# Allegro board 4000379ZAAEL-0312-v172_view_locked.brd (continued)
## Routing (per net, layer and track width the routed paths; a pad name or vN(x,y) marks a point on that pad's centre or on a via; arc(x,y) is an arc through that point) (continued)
DDR_A5: length 88
  TOP w0.102: U13.P2 96.57,25.59 96.96,25.99 v1(96.96,26.02) ; v1(103.76,36.75) 103.94,36.93 103.94,37.49 102.58,38.85 102.58,43.55 102.62,43.59 U1.B20 ; v1(117.34,26.02) 117.34,25.99 116.94,25.59 U12.P2
  BOTTOM w0.102: R110.2 121.34,27.64 121.31,27.64 121.16,27.49 119.39,27.49 118.45,26.55 117.43,26.55 117.34,26.46 v1(117.34,26.02) 117.17,26.02 116.73,25.58 116.4,25.58 116.11,25.86 116.11,26.26 115.84,26.53 115.3,26.53 114.32,27.52 112.45,27.52 111.27,28.7 109.2,28.7 108.29,27.79 103.91,27.79 103.84,27.71 103.84,27.28 103.76,27.2 103.5,27.2 103.43,27.28 103.43,27.71 103.35,27.79 102.54,27.79 102.46,27.71 102.46,27.43 102.54,27.36 102.95,27.36 103.02,27.28 103.02,26.97 102.95,26.9 102.11,26.9 101.3,26.09 97.06,26.09 97,26.02 v1(96.96,26.02) 96.95,26.01 96.84,26.01 96.38,25.56 96.02,25.56 95.73,25.84 95.73,26.21 95.52,26.43 94.83,26.43 93.76,27.51 91.97,27.51 91.57,27.91 91.57,28.05 90.53,29.09 90.53,31.57 90.6,31.65 93.65,31.65 93.73,31.72 93.73,33.93 93.8,34.01 99.14,34.01 99.21,34.09 99.21,35.23 99.29,35.31 101.57,35.31 101.65,35.38 101.65,35.89 101.73,35.97 104.39,35.97 104.47,36.04 104.47,36.45 104.55,36.53 109.55,36.53 109.63,36.6 109.63,37.85 109.7,37.92 109.86,37.92 109.93,38 109.93,38.25 109.86,38.33 109.7,38.33 109.63,38.4 109.63,38.66 109.7,38.73 109.86,38.73 109.93,38.81 109.93,39.07 109.86,39.14 109.3,39.14 109.22,39.07 109.22,36.98 109.14,36.91 108.89,36.91 108.81,36.98 108.81,37.74 108.74,37.82 108.48,37.82 108.41,37.74 108.41,36.98 108.33,36.91 103.91,36.91 v1(103.76,36.75)
DDR_A6: length 93
  TOP w0.102: U12.R8 112.14,26.39 112.5,26.75 112.5,28.35 v1(112.51,28.36) ; v1(103.1,34.85) 103.59,35.34 103.59,35.92 104.04,36.37 104.34,36.37 104.47,36.5 104.47,37.39 102.81,39.05 102.81,44.22 102.97,44.38 102.97,44.58 102.62,44.92 102.62,45.33 U1.D20 ; v1(92.18,28.24) 92.15,28.22 92.15,26.77 91.77,26.39 U13.R8
  BOTTOM w0.102: R111.2 121.36,28.53 118.78,28.53 118.7,28.45 118.7,27.54 118.18,27.02 115.39,27.02 114.49,27.93 113.12,27.93 112.69,28.36 v1(112.51,28.36) 112.22,28.36 111.47,29.11 109,29.11 108.14,28.24 101.22,28.24 101.14,28.17 101.14,27.71 101.04,27.61 100.61,27.61 100.48,27.74 98.52,27.74 97.66,26.89 94.95,26.89 93.92,27.91 92.75,27.91 92.68,27.98 92.57,27.98 92.51,27.91 92.37,27.91 92.18,28.11 v1(92.18,28.24) 91.97,28.24 91.14,29.08 91.14,30.96 91.21,31.04 94.26,31.04 94.34,31.11 94.34,33.32 94.41,33.4 99.75,33.4 99.82,33.48 99.82,34.62 99.9,34.7 102.41,34.7 102.49,34.77 102.49,35.28 102.57,35.36 103.63,35.36 103.71,35.28 103.71,35.15 103.78,35.08 104.78,35.08 104.85,35.15 104.85,36.22 104.93,36.3 110.16,36.3 110.24,36.37 110.24,37.39 110.31,37.47 110.57,37.47 110.64,37.39 110.64,36.37 110.72,36.3 110.97,36.3 111.05,36.37 111.05,37.39 111.12,37.47 111.38,37.47 111.46,37.39 111.46,35.97 111.38,35.89 105.31,35.89 105.23,35.81 105.23,34.77 105.16,34.7 103.25,34.7 v1(103.1,34.85)
DDR_A7: length 84.6
  TOP w0.102: v1(103.1,33.02) 103.4,33.32 103.4,34.4 103.87,34.87 103.87,35.84 104.1,36.06 104.62,36.06 104.78,36.22 104.78,37.52 103.05,39.24 103.05,43.78 U1.A19 ; v1(117.42,28.24) 117.42,28.24 117.4,28.24 117.32,28.17 117.32,26.77 116.94,26.39 U12.R2 ; U13.R2 96.57,26.39 96.96,26.78 96.96,28.15 97.04,28.23 v1(97.04,28.24)
  BOTTOM w0.102: v1(103.1,33.02) 103.53,33.02 104.25,32.26 111.63,32.26 111.71,32.18 111.71,31.93 111.61,31.83 111.43,31.83 111.35,31.75 111.35,31.42 111.28,31.34 111.02,31.34 110.95,31.42 110.95,31.75 110.87,31.83 110.62,31.83 110.54,31.75 110.54,31.42 110.46,31.34 110.21,31.34 110.13,31.42 110.13,31.75 110.06,31.83 109.8,31.83 109.73,31.75 109.73,31.42 109.65,31.34 109.4,31.34 109.32,31.42 109.32,31.75 109.25,31.83 108.99,31.83 108.92,31.75 108.92,31.42 108.84,31.34 108.58,31.34 108.51,31.42 108.51,31.75 108.43,31.83 108.18,31.83 108.1,31.75 108.1,31.42 108.03,31.34 107.77,31.34 107.7,31.42 107.7,31.75 107.62,31.83 107.37,31.83 107.29,31.75 107.29,31.42 107.21,31.34 106.96,31.34 106.88,31.42 106.88,31.75 106.81,31.83 106.55,31.83 106.48,31.75 106.48,31.42 106.4,31.34 106.15,31.34 106.07,31.42 106.07,31.75 105.99,31.83 105.74,31.83 105.66,31.75 105.66,31.42 105.59,31.34 105.33,31.34 105.26,31.42 105.26,31.75 105.18,31.83 104.93,31.83 104.85,31.75 104.85,31.42 104.78,31.34 104.52,31.34 104.44,31.42 104.44,31.75 104.37,31.83 104.11,31.83 104.04,31.75 104.04,31.42 103.96,31.34 103.73,31.34 103.63,31.45 103.63,32.33 103.43,32.54 102.9,32.54 102.34,33.1 101.45,33.1 101.32,32.97 101.32,31.95 101.24,31.88 95.94,31.88 95.86,31.8 95.86,29.9 94.94,28.98 94.94,28.37 95.2,28.11 95.66,28.11 95.97,28.42 96.88,28.42 97.04,28.26 v1(97.04,28.24) 97.41,28.24 98.7,29.54 99.01,29.54 99.26,29.29 99.57,29.29 99.82,29.54 107.8,29.54 107.9,29.64 107.9,30.05 107.97,30.12 113.73,30.12 115.69,28.16 116.04,28.16 116.34,28.46 117.21,28.46 v1(117.42,28.24) 117.66,28.48 117.66,31.75 117.58,31.82 R112.2
DDR_A8: length 91.5
  TOP w0.102: v1(105.69,35.31) 105.23,35.31 105.08,35.46 105.08,37.64 103.28,39.44 103.28,44.26 103.17,44.37 103.17,44.8 103.06,44.92 U1.C19 ; U12.T8 112.01,27.3 112.01,29.01 v1(112.09,29.08) ; U13.T8 91.77,27.19 91.65,27.3 91.65,29.09 v1(91.69,29.13)
  BOTTOM w0.102: R113.2 118.93,29.08 118.5,28.65 118.5,27.75 117.98,27.23 115.47,27.23 114.57,28.13 113.36,28.13 112.73,28.77 112.37,28.77 112.09,29.04 v1(112.09,29.08) 112.05,29.08 111.82,29.31 108.9,29.31 108.06,28.47 101.04,28.47 100.57,28.01 100.13,28.01 100.08,28.06 100.08,28.24 100,28.32 99.69,28.32 99.62,28.24 99.62,28.08 99.54,28.01 99.24,28.01 99.16,28.08 99.16,28.24 99.09,28.32 98.78,28.32 97.57,27.11 95.01,27.11 94.01,28.12 92.89,28.12 92.3,28.7 91.91,28.7 91.69,28.92 v1(91.69,29.13) 91.44,29.39 91.44,29.74 91.52,29.82 92.05,29.82 92.13,29.9 92.13,30.2 92.05,30.28 91.52,30.28 91.44,30.35 91.44,30.66 91.52,30.73 94.56,30.73 94.64,30.81 94.64,33.02 94.72,33.1 100.05,33.1 100.13,33.17 100.13,34.32 100.2,34.39 105.69,34.39 105.87,34.57 106.4,34.57 106.45,34.52 106.45,33.78 106.53,33.71 106.81,33.71 106.88,33.78 106.88,34.49 106.96,34.57 107.21,34.57 107.29,34.49 107.29,33.78 107.37,33.71 107.62,33.71 107.7,33.78 107.7,34.49 107.77,34.57 108.03,34.57 108.1,34.49 108.1,33.78 108.18,33.71 108.43,33.71 108.51,33.78 108.51,34.7 108.58,34.77 108.84,34.77 108.92,34.7 108.92,33.78 108.99,33.71 109.25,33.71 109.32,33.78 109.32,34.7 109.4,34.77 109.65,34.77 109.73,34.7 109.73,33.78 109.8,33.71 110.9,33.71 110.97,33.78 110.97,34.24 110.9,34.32 110.19,34.32 110.11,34.39 110.11,34.7 110.19,34.77 110.95,34.77 111.02,34.85 111.02,35.08 110.92,35.18 108,35.18 107.8,34.98 107.09,34.98 106.98,35.08 106.98,35.53 106.91,35.61 106.68,35.61 106.6,35.53 106.6,35.05 106.53,34.98 106.22,34.98 106.15,35.05 106.15,35.53 106.07,35.61 105.77,35.61 105.69,35.53 v1(105.69,35.31)
DDR_A9: length 85.8
  TOP w0.102: v1(104.22,32.99) 104.22,33.99 104.32,34.09 105.49,34.09 105.56,34.01 105.56,33.32 105.64,33.25 106.22,33.25 106.3,33.32 106.3,33.55 106.07,33.78 106.07,33.91 106.3,34.14 106.3,36.22 106.22,36.3 105.94,36.3 105.87,36.22 105.87,35.97 105.79,35.89 105.46,35.89 105.38,35.97 105.38,36.68 105.46,36.75 108.13,36.75 108.2,36.83 108.2,37.29 108.13,37.36 105.46,37.36 105.38,37.44 105.38,37.77 103.49,39.67 103.49,44.42 ; v1(96.19,28.02) 96.19,28.01 96.2,27.99 96.2,26.82 95.77,26.39 U13.R3 ; v1(116.56,28.05) 116.56,28.02 116.64,27.94 116.53,27.84 116.53,26.79 116.14,26.39 U12.R3
  TOP w0.114: 103.49,44.42 103.49,44.43 103.43,44.49 103.48,44.49 ; U1.B18 103.48,44.49 ; 103.48,44.49 103.49,44.49
  BOTTOM w0.102: v1(104.22,32.99) 104.56,32.56 111.02,32.56 111.1,32.64 111.1,32.94 111.02,33.02 105.94,33.02 105.87,33.1 105.87,33.71 105.79,33.78 105.54,33.78 105.46,33.71 105.46,33.28 105.33,33.15 104.75,33.15 104.44,33.45 101.12,33.45 101.04,33.38 101.04,32.26 100.97,32.18 95.63,32.18 95.55,32.11 95.55,29.97 95.22,29.63 95.06,29.63 94.9,29.8 94.72,29.8 94.63,29.71 94.63,29.53 94.73,29.43 94.73,29.3 94.63,29.2 94.63,28.36 95.18,27.81 95.99,27.81 v1(96.19,28.02) 96.37,27.84 97.32,27.84 98.57,29.08 99.82,29.08 99.97,29.24 100.13,29.24 100.28,29.08 100.48,29.08 100.63,29.24 100.84,29.24 100.99,29.08 101.14,29.08 101.3,29.24 101.5,29.24 101.65,29.08 101.85,29.08 102.06,29.29 102.21,29.29 102.41,29.08 102.57,29.08 102.77,29.29 102.92,29.29 103.12,29.08 103.28,29.08 103.48,29.29 103.68,29.29 103.89,29.08 104.04,29.08 104.24,29.29 104.39,29.29 104.6,29.08 104.75,29.08 104.95,29.29 107.95,29.29 108.58,29.92 113.64,29.92 115.67,27.89 116.23,27.89 116.4,28.05 v1(116.56,28.05) 116.82,27.84 117.61,27.84 117.89,28.12 117.89,29.72 117.97,29.79 118.01,29.79 R114.2
DDR_A10: length 94.4
  TOP w0.102: U13.L7 92.57,23.19 92.78,22.97 93.05,22.97 v1(93.07,22.96) ; v1(113.49,22.96) 113.15,22.97 112.94,23.19 U12.L7 ; v1(104.04,40.67) 103.79,40.67 103.69,40.77 103.69,44.26 103.82,44.39 103.82,44.59 103.49,44.92 103.49,45.33 U1.D18
  BOTTOM w0.102: v1(104.04,40.67) 103.86,40.84 102.99,40.84 102.92,40.77 102.92,40.34 102.84,40.26 102.59,40.26 102.51,40.34 102.51,40.77 102.44,40.85 102.18,40.85 102.11,40.77 102.11,40.34 102.03,40.26 101.78,40.26 101.7,40.34 101.7,40.77 101.63,40.85 93.55,40.85 93.47,40.77 93.47,40.62 93.39,40.54 93.14,40.54 93.07,40.62 93.07,40.79 92.99,40.87 92.74,40.87 92.66,40.79 92.66,40.61 92.59,40.54 92.33,40.54 92.25,40.62 92.25,40.79 92.18,40.87 91.92,40.87 91.85,40.79 91.85,40.59 91.8,40.54 91.52,40.54 91.44,40.62 91.44,40.79 91.36,40.87 91.11,40.87 91.03,40.79 91.03,40.62 90.96,40.54 90.7,40.54 90.63,40.62 90.63,40.79 90.55,40.87 90.3,40.87 90.22,40.79 90.22,40.61 90.15,40.54 89.89,40.54 89.81,40.62 89.81,40.79 89.74,40.87 89.48,40.87 89.41,40.79 89.41,40.62 89.33,40.54 87.27,40.54 83.52,36.79 83.52,24.41 85.12,22.81 86.94,22.81 87.02,22.89 87.02,24.13 87.12,24.23 88.7,24.23 88.82,24.1 89.83,24.1 90.55,23.38 90.78,23.38 90.92,23.24 91.3,23.24 91.44,23.38 92.52,23.38 92.94,22.96 v1(93.07,22.96) 93.35,22.96 94.95,21.36 105.49,21.36 105.56,21.44 105.56,22.2 105.64,22.28 105.89,22.28 105.97,22.2 105.97,21.46 106.05,21.39 106.27,21.39 106.38,21.49 106.38,23.24 106.45,23.32 106.65,23.32 106.73,23.24 106.73,23.11 106.81,23.04 107.06,23.04 107.14,23.11 107.14,23.24 107.21,23.32 108.29,23.32 108.9,23.93 109.51,23.93 110.05,23.38 112.99,23.38 113.39,22.97 v1(113.49,22.96) 113.76,22.97 115.44,21.3 119.65,21.3 121.16,19.79 123.18,19.79 R115.2
DDR_A11: length 90.8
  TOP w0.102: U13.R7 92.57,26.39 93.17,26.99 v1(93.17,28.73) ; U12.R7 112.94,26.39 113.54,26.99 v1(113.54,28.89) ; U1.A17 103.92,44.09 103.92,41.55 104.62,40.84 104.62,40.46 104.34,40.18 103.86,40.18 103.78,40.11 103.78,39.73 103.86,39.65 104.32,39.65 104.4,39.57 104.4,39.3 105.31,38.38 105.59,38.38 105.84,38.13 105.84,37.79 105.96,37.67 108.41,37.67 108.51,37.57 108.51,36.55 108.41,36.45 106.76,36.45 106.68,36.37 106.68,31.14 106.55,31.01 106.25,31.01 106.17,31.09 106.17,32.77 106.1,32.84 105.33,32.84 105.26,32.77 105.26,32.41 105.33,32.33 105.61,32.33 105.69,32.26 105.69,31.04 105.61,30.96 104.22,30.96 104.14,31.04 104.14,31.34 104.22,31.42 105.08,31.42 105.16,31.5 105.16,31.85 105.08,31.93 104.01,31.93 103.94,32 103.94,32.36 104.01,32.44 104.67,32.44 104.75,32.51 104.75,33.45 v1(104.93,33.63)
  BOTTOM w0.102: v1(104.93,33.63) 104.86,33.78 100.81,33.78 100.74,33.71 100.74,32.56 100.66,32.49 95.33,32.49 95.25,32.41 95.25,30.2 95.17,30.12 92.81,30.12 92.74,30.05 92.74,29.9 92.81,29.82 94.26,29.82 94.34,29.74 94.34,29.59 94.26,29.51 93.04,29.51 92.96,29.44 92.96,29.24 93.04,29.16 94.21,29.16 94.28,29.08 94.28,28.96 94.21,28.88 93.24,28.88 93.17,28.8 v1(93.17,28.73) 93.37,28.52 94.18,28.52 95.13,27.57 97.38,27.57 98.69,28.88 105.05,28.88 105.21,29.03 108.01,29.03 108.69,29.72 112.8,29.72 113.54,28.98 v1(113.54,28.89) 113.54,28.83 113.64,28.73 114.55,28.73 115.64,27.63 117.72,27.63 118.09,28.01 118.09,29.12 118.61,29.63 R116.2
DDR_A12: length 92.6
  TOP w0.102: U1.C17 103.92,44.92 104.04,44.81 104.04,44.39 104.15,44.28 104.15,41.78 104.85,41.07 v1(104.85,39.93) ; v1(113.41,24.43) 113.06,24.79 112.94,24.79 U12.N7 ; v1(93.04,24.43) 93.04,24.47 92.89,24.47 92.57,24.79 U13.N7
  BOTTOM w0.102: v1(104.85,39.93) 105.24,40.32 106.23,40.32 106.62,40.7 106.62,41.58 106.68,41.64 107.28,41.64 107.37,41.55 107.37,40.74 106.43,39.8 105.56,39.8 105.11,39.34 104.56,39.34 104.28,39.63 87.65,39.63 84.43,36.41 84.43,25.25 84.53,25.15 88.37,25.15 88.44,25.22 88.44,25.55 88.52,25.63 88.83,25.63 88.91,25.55 88.91,24.94 89.13,24.71 90.08,24.71 90.8,23.99 91.92,23.99 92.37,24.43 v1(93.04,24.43) 94.01,23.47 94.01,23.29 94.79,22.5 95.28,22.5 95.81,21.97 104.5,21.97 104.6,22.07 104.6,22.2 104.52,22.28 104.34,22.28 104.27,22.35 104.27,22.5 104.34,22.58 104.52,22.58 104.6,22.66 104.6,22.86 104.52,22.94 104.34,22.94 104.27,23.01 104.27,23.16 104.34,23.24 104.52,23.24 104.6,23.32 104.6,23.52 104.52,23.6 104.34,23.6 104.27,23.67 104.27,23.9 104.34,23.98 108.08,23.98 108.64,24.54 109.83,24.54 110.37,23.99 112.34,23.99 112.78,24.43 v1(113.41,24.43) 113.45,24.43 114.79,23.09 114.79,22.8 115.16,22.44 115.75,22.44 116.27,21.92 120.35,21.92 120.97,21.3 121.28,21.3 R118.2
DDR_A13: length 85.6
  TOP w0.102: v1(115.85,28.61) 115.85,28.55 116.1,28.3 116.1,27.23 116.14,27.19 U12.T3 ; 104.35,44.41 104.35,42 105.31,41.04 105.31,39.55 105.1,39.33 105.1,39.08 105.46,38.71 105.71,38.71 106.45,37.97 108.66,37.97 108.79,37.85 108.79,34.65 108.71,34.57 108.08,34.57 108,34.49 108,34.24 108.08,34.16 108.71,34.16 108.79,34.09 108.79,33.83 108.71,33.76 108.08,33.76 108,33.68 108,33.43 108.08,33.35 108.71,33.35 108.79,33.27 108.79,33.02 108.71,32.94 108.08,32.94 108,32.87 108,32.61 108.08,32.54 108.71,32.54 108.79,32.46 108.79,32.03 108.71,31.95 107.67,31.95 107.59,32.03 107.59,34.9 107.67,34.98 108.13,34.98 108.2,35.05 108.2,36.02 108.13,36.09 107.06,36.09 106.98,36.02 106.98,30.73 106.91,30.66 106.55,30.66 106.48,30.58 106.48,30.18 106.4,30.1 106.15,30.1 106.07,30.18 106.07,30.58 105.99,30.66 105.74,30.66 105.66,30.58 105.66,29.99 105.59,29.91 105.33,29.91 105.26,29.99 105.26,30.58 105.18,30.66 104.93,30.66 104.85,30.58 104.85,29.98 104.78,29.91 104.52,29.91 104.44,29.98 104.44,30.58 104.37,30.66 104.11,30.66 104.04,30.58 104.04,29.97 103.96,29.9 103.1,29.9 103.02,29.97 103.02,30.23 103.1,30.3 103.56,30.3 103.63,30.38 103.63,31.75 103.56,31.83 v1(103.02,31.83) ; v1(95.45,28.52) 95.5,28.52 95.74,28.29 95.74,27.22 95.77,27.19 U13.T3
  TOP w0.114: 104.35,44.49 104.35,44.49 ; 104.35,44.49 104.28,44.49 104.35,44.42 104.35,44.41 ; 104.35,44.49 U1.B16
  BOTTOM w0.102: v1(103.02,31.83) 103.02,31.95 102.41,32.56 101.78,32.56 101.63,32.41 101.63,31.65 101.55,31.57 96.24,31.57 96.16,31.5 96.16,29.57 95.45,28.85 v1(95.45,28.52) 95.54,28.52 95.68,28.66 97.47,28.66 98.56,29.76 104.32,29.76 104.39,29.83 104.39,29.97 104.47,30.05 104.88,30.05 104.95,29.97 104.95,29.83 105.03,29.76 105.33,29.76 105.41,29.83 105.41,30.23 105.49,30.3 105.94,30.3 106.02,30.23 106.02,29.83 106.1,29.76 106.45,29.76 106.53,29.83 106.53,30.23 106.6,30.3 107.02,30.3 107.09,30.23 107.09,29.85 107.19,29.76 107.48,29.76 107.62,29.9 107.62,30.15 107.8,30.33 114.07,30.33 115.79,28.61 v1(115.85,28.61) 115.96,28.61 116.04,28.69 117.3,28.69 117.4,28.79 117.4,29.68 117,30.08 116.94,30.08 R119.2
DDR_A14: length 88.7
  TOP w0.102: v1(107.44,35.46) 107.29,35.31 107.29,31.7 107.37,31.62 108.99,31.62 109.12,31.75 109.12,39.52 108.99,39.65 108.38,39.65 107.17,40.86 107.17,43.34 106.51,44 106.51,44.09 U1.A11 ; v1(92.44,29.11) 92.59,28.98 92.59,27.19 92.57,27.19 U13.T7 ; v1(112.74,29.19) 113,28.94 113,27.25 112.94,27.19 U12.T7
  BOTTOM w0.102: v1(107.44,35.46) 107.44,35.48 111.86,35.48 111.94,35.41 111.94,35.15 111.86,35.08 111.43,35.08 111.35,35 111.35,34.75 111.43,34.67 111.86,34.67 111.94,34.59 111.94,34.34 111.86,34.26 111.43,34.26 111.35,34.19 111.35,33.93 111.43,33.86 111.86,33.86 111.94,33.78 111.94,33.48 111.86,33.4 106.22,33.4 106.15,33.48 106.15,34.01 106.07,34.09 100.51,34.09 100.43,34.01 100.43,32.87 100.36,32.79 95.02,32.79 94.95,32.72 94.95,30.51 94.87,30.43 92.52,30.43 92.44,30.35 v1(92.44,29.11) 92.44,28.87 92.99,28.32 94.09,28.32 95.07,27.34 97.48,27.34 98.71,28.57 100.74,28.57 100.84,28.68 105.31,28.68 105.46,28.83 105.61,28.83 105.77,28.68 105.92,28.68 106.07,28.83 106.22,28.83 106.38,28.68 106.53,28.68 106.68,28.83 106.88,28.83 107.04,28.68 107.19,28.68 107.34,28.83 107.54,28.83 107.7,28.68 107.96,28.68 108.8,29.51 112.42,29.51 v1(112.74,29.19) 112.78,29.16 112.78,29.03 113.48,28.33 114.66,28.33 115.56,27.43 117.84,27.43 118.3,27.89 118.3,28.95 119.11,29.77 119.11,29.97 R120.2
DDR_A15: length 89.6
  TOP w0.102: U13.M7 92.57,23.99 92.6,23.99 v1(92.96,23.62) ; U12.M7 112.94,23.99 113.3,23.62 v1(113.39,23.62) ; v1(101.21,40.39) 101.33,40.51 101.33,41.1 101.12,41.31 101.12,41.57 101.33,41.78 101.33,41.94 101.1,42.16 101.1,42.32 101.33,42.55 101.33,44.09 U1.A23
  BOTTOM w0.102: v1(101.21,40.39) 101.05,40.54 100.89,40.54 100.77,40.43 100.77,40.31 100.7,40.24 100.43,40.24 100.36,40.31 100.36,40.47 100.28,40.54 100.03,40.54 99.95,40.47 99.95,40.31 99.87,40.24 99.62,40.24 99.54,40.31 99.54,40.47 99.47,40.54 99.21,40.54 99.14,40.47 99.14,40.31 99.06,40.24 98.81,40.24 98.73,40.31 98.73,40.47 98.65,40.54 98.4,40.54 98.32,40.47 98.32,40.31 98.25,40.24 97.99,40.24 97.92,40.31 97.92,40.47 97.84,40.54 97.59,40.54 97.51,40.47 97.51,40.31 97.43,40.24 97.18,40.24 97.1,40.31 97.1,40.47 97.03,40.54 96.77,40.54 96.7,40.47 96.7,40.31 96.62,40.24 96.37,40.24 96.29,40.31 96.29,40.48 96.22,40.55 95.96,40.55 95.89,40.48 95.89,40.31 95.81,40.24 95.55,40.24 95.48,40.31 95.48,40.47 95.4,40.54 95.15,40.54 95.07,40.47 95.07,40.31 95,40.24 94.74,40.24 94.67,40.31 94.67,40.49 94.59,40.56 93.9,40.56 93.57,40.24 87.4,40.24 83.82,36.66 83.82,24.54 84.79,23.57 85.34,23.57 85.45,23.47 85.45,23.19 85.52,23.11 85.78,23.11 85.85,23.19 85.85,24.41 85.93,24.49 86.18,24.49 86.26,24.41 86.26,23.16 86.31,23.11 86.66,23.11 86.72,23.16 86.72,23.24 86.64,23.32 86.64,23.39 86.72,23.47 86.72,23.57 86.64,23.65 86.64,23.75 86.72,23.83 86.72,23.93 86.64,24 86.64,24.08 86.72,24.16 86.72,24.46 86.79,24.54 88.7,24.54 88.93,24.31 89.91,24.31 90.64,23.58 92.18,23.58 92.42,23.83 92.76,23.83 v1(92.96,23.62) 92.99,23.62 95.05,21.56 105.26,21.56 105.36,21.67 105.36,22.45 105.44,22.53 106.05,22.53 106.12,22.61 106.12,22.76 106.05,22.83 105.44,22.83 105.36,22.91 105.36,23.42 105.44,23.5 105.59,23.5 105.66,23.42 105.66,23.19 105.74,23.11 106.05,23.11 106.12,23.19 106.12,23.45 106.19,23.52 108.2,23.52 108.81,24.13 109.61,24.13 110.16,23.58 113.33,23.58 113.36,23.62 v1(113.39,23.62) 113.69,23.62 114.24,23.07 114.24,22.78 115.52,21.5 119.81,21.5 120.94,20.37 R121.2
DDR_ALERT: length 1.3
  TOP w0.127: U1.F12 106.1,46.18 106.43,45.85 v1(106.48,45.85)
  BOTTOM w0.102: R132.2 106.43,45.8 v1(106.48,45.85)
DDR_BA_0: length 88.5
  TOP w0.102: U12.M2 116.94,23.99 v1(116.51,24.41) ; v1(96.18,24.41) 96.18,24.38 96.57,23.99 U13.M2 ; U1.B12 106.08,44.5 106.08,43.87 106.76,43.19 106.76,39.93 107.09,39.6 107.09,38.51 107.16,38.43 107.42,38.43 107.49,38.51 107.49,38.79 107.57,38.86 107.82,38.86 107.9,38.79 107.9,38.51 107.98,38.43 108.48,38.43 v1(108.69,38.63)
  BOTTOM w0.102: v1(108.69,38.63) 107.26,37.21 107.26,37.21 103.68,37.21 103.38,37.52 102.83,37.52 102.22,36.91 101.25,36.91 100.94,37.21 88.68,37.21 87.19,35.72 87.19,35.46 87.27,35.38 88.01,35.38 88.09,35.46 88.09,36.12 88.16,36.2 88.42,36.2 88.49,36.12 88.49,35.46 88.57,35.38 88.82,35.38 88.9,35.46 88.9,35.76 88.98,35.84 89.23,35.84 89.31,35.76 89.31,35.05 89.23,34.98 88.16,34.98 88.09,34.9 88.09,34.65 88.16,34.57 88.85,34.57 88.93,34.49 88.93,34.24 88.85,34.16 88.32,34.16 88.24,34.09 88.24,33.83 88.32,33.76 88.85,33.76 88.93,33.68 88.93,33.02 89,32.94 89.23,32.94 89.31,32.87 89.31,29.15 90.73,27.73 90.73,27.28 90.91,27.1 90.91,26.37 91.08,26.19 91.63,26.19 92.14,26.7 93.42,26.7 95.05,25.06 95.35,25.06 96.02,24.39 96.16,24.39 v1(96.18,24.41) 96.19,24.41 96.37,24.59 101.27,24.59 102.51,25.83 105.33,25.83 105.41,25.91 105.41,26.42 105.49,26.49 105.74,26.49 105.82,26.42 105.82,25.91 105.89,25.83 106.15,25.83 106.22,25.91 106.22,26.85 106.3,26.92 108.66,26.92 109.62,27.89 110.93,27.89 111.28,27.54 111.28,26.6 111.46,26.42 112.05,26.42 112.34,26.71 113.84,26.71 115.44,25.11 115.67,25.11 116.37,24.41 v1(116.51,24.41) 116.67,24.41 116.7,24.38 120.19,24.38 121.23,25.43 R123.2
DDR_BA_1: length 96
  TOP w0.102: U1.D12 106.08,45.33 106.08,44.92 106.41,44.59 106.41,44.37 106.28,44.25 106.28,43.96 106.96,43.27 106.96,40.15 107.06,40.06 107.37,40.06 107.45,39.97 107.45,39.48 107.54,39.4 v1(107.95,39.4) ; 91.76,24.79 91.77,24.79 ; 91.76,24.79 v1(91.34,25.21) ; 91.76,24.79 U13.N8 ; U12.N8 112.14,24.79 111.72,25.2 v1(111.72,25.22)
  BOTTOM w0.102: v1(107.95,39.4) 107.94,39.38 107.94,39.03 106.73,37.82 103.93,37.82 103.65,38.1 88.28,38.1 85.95,35.78 85.95,27.51 86,27.46 86.72,27.46 86.77,27.51 86.77,27.91 86.72,27.97 86.41,27.97 86.36,28.02 86.36,29.51 86.44,29.59 86.69,29.59 86.77,29.51 86.77,28.75 86.84,28.68 87.2,28.68 87.27,28.75 87.27,29.51 87.35,29.59 87.6,29.59 87.68,29.51 87.68,28.35 87.6,28.27 87.25,28.27 87.17,28.19 87.17,27.91 87.25,27.84 88.01,27.84 88.09,27.91 88.09,29.51 88.16,29.59 88.39,29.59 88.47,29.51 88.47,27.76 91.02,25.21 v1(91.34,25.21) 91.65,25.21 92.11,25.68 93.57,25.68 94.54,24.71 94.54,24.42 95.01,23.95 95.44,23.95 95.8,23.6 96.62,23.6 97,23.98 99.21,23.98 99.29,23.9 99.29,23.37 99.36,23.29 99.61,23.29 99.68,23.37 99.68,23.9 99.76,23.98 100.04,23.98 100.11,23.9 100.11,23.44 100.19,23.37 101.08,23.37 102.78,25.07 107.74,25.07 108.49,25.82 108.49,26 108.75,26.26 109.04,26.26 109.1,26.32 110.03,26.32 110.55,25.79 111.48,25.79 111.57,25.7 111.57,25.36 111.7,25.22 v1(111.72,25.22) 112.06,25.22 112.51,25.67 113.94,25.67 114.87,24.74 114.87,24.45 115.4,23.93 115.83,23.93 116.23,23.52 116.8,23.52 117.05,23.77 120.85,23.77 120.96,23.88 123.23,23.88 R124.2
DDR_BA_2/BG_0: length 91.3
  TOP w0.102: v1(115.61,24.59) 115.61,24.56 115.62,24.55 115.62,24.5 116.14,23.99 U12.M3 ; v1(108.86,40.23) 108.16,40.23 107.37,41.02 107.37,43.43 106.86,43.94 106.86,44.14 106.61,44.39 106.61,44.8 106.51,44.9 106.51,44.92 U1.C11 ; v1(95.23,24.6) 95.23,24.53 95.77,23.99 U13.M3
  BOTTOM w0.102: R125.2 123.26,25.02 123.18,24.94 121.14,24.94 120.38,24.18 116.88,24.18 116.63,23.93 116.4,23.93 115.74,24.59 v1(115.61,24.59) 115.61,24.65 113.75,26.5 112.44,26.5 112.15,26.21 110.77,26.21 110.26,26.72 108.82,26.72 108.76,26.67 107.42,26.67 107.34,26.59 107.34,25.8 107.26,25.72 107.01,25.72 106.93,25.8 106.93,26.59 106.86,26.67 106.6,26.67 106.53,26.59 106.53,25.65 106.45,25.58 102.62,25.58 101.42,24.38 96.82,24.38 96.44,24 95.97,24 95.38,24.59 95.24,24.59 v1(95.23,24.6) 93.33,26.49 92.26,26.49 91.75,25.98 90.82,25.98 89,27.81 89,32.56 88.93,32.64 87.68,32.64 87.6,32.72 87.6,32.97 87.68,33.05 88.54,33.05 88.62,33.12 88.62,33.38 88.54,33.45 86.64,33.45 86.56,33.53 86.56,33.78 86.64,33.86 87.86,33.86 87.93,33.93 87.93,34.19 87.86,34.26 86.64,34.26 86.56,34.34 86.56,34.59 86.64,34.67 87.71,34.67 87.78,34.75 87.78,35 87.71,35.08 86.64,35.08 86.56,35.15 86.56,35.52 88.56,37.52 101.07,37.52 101.38,37.21 102.08,37.21 102.69,37.82 103.5,37.82 103.81,37.52 106.93,37.52 108.86,39.45 v1(108.86,40.23)
DDR_BL0_DQ0: length 39.9
  TOP w0.102: U1.G2 110.01,46.48 111.01,46.48 111.9,45.59 112.97,45.59 114.25,44.32 114.25,43.92 114.32,43.84 114.68,43.84 114.76,43.76 114.76,43.48 114.68,43.41 114.26,43.41 114.19,43.33 114.19,43.08 114.26,43 115.29,43 115.37,42.93 115.37,42.67 115.29,42.6 114.26,42.6 114.19,42.52 114.19,42.27 114.26,42.19 115.24,42.19 115.37,42.06 115.37,32.85 120.85,27.37 120.85,20.73 119.66,19.53 118.75,19.53 118.57,19.71 118.06,19.71 117.94,19.59 117.34,19.59 116.94,19.19 U12.F2
DDR_BL0_DQ1: length 39.2
  TOP w0.102: U12.F7 112.94,19.19 112.52,18.77 111.11,18.77 110.94,18.6 110.57,18.6 110.24,18.93 110.24,19.15 110.16,19.23 109.91,19.23 109.83,19.15 109.83,18.97 109.75,18.9 109.5,18.9 109.42,18.97 109.42,19.15 109.35,19.23 109.09,19.23 109.02,19.15 109.02,18.9 108.94,18.82 108.69,18.82 108.61,18.9 108.61,19.15 108.53,19.23 105.71,19.23 105.61,19.33 105.61,28.91 105.77,29.06 108.61,29.06 109.73,30.18 109.73,41.62 108.2,43.15 108.2,44.27 108.62,44.69 U1.B4
DDR_BL0_DQ2: length 39.1
  TOP w0.102: U1.F3 110.05,46.06 110.27,46.28 110.93,46.28 111.87,45.34 112.8,45.34 113.88,44.26 113.88,42 114,41.88 114.99,41.88 115.06,41.81 115.06,41.55 114.99,41.48 114.48,41.48 114.4,41.4 114.4,41.15 114.48,41.07 114.96,41.07 115.06,40.97 115.06,40.74 114.99,40.67 114.5,40.67 114.43,40.59 114.43,40.34 114.5,40.26 114.94,40.26 115.06,40.14 115.06,39.95 114.99,39.88 114.5,39.88 114.43,39.8 114.43,39.5 114.5,39.42 114.99,39.42 115.06,39.34 115.06,32.73 120.55,27.24 120.55,21.31 119.66,20.43 118.93,20.43 118.72,20.22 118.05,20.22 117.84,20.43 117.38,20.43 116.94,19.99 U12.G2
DDR_BL0_DQ3: length 38.9
  TOP w0.102: 112.13,20.79 111.93,20.79 111.53,21.18 110.9,21.18 110.83,21.26 110.83,21.61 110.75,21.69 109.69,21.69 109.61,21.61 109.61,21.39 109.53,21.31 109.28,21.31 109.2,21.39 109.2,21.61 109.13,21.69 108.75,21.69 108.67,21.61 108.67,21.41 108.59,21.33 108.31,21.33 108.24,21.41 108.24,21.61 108.16,21.69 107.57,21.69 107.49,21.61 107.49,21.23 107.57,21.16 107.72,21.16 107.8,21.08 107.8,20.83 107.72,20.75 106.63,20.75 106.55,20.83 106.55,21.08 106.63,21.16 106.98,21.16 107.06,21.23 107.06,21.49 106.98,21.56 106.6,21.56 106.53,21.64 106.53,21.89 106.6,21.97 106.98,21.97 107.06,22.05 107.06,22.3 106.98,22.38 106.6,22.38 106.53,22.45 106.53,22.71 106.6,22.78 106.98,22.78 107.06,22.86 107.06,23.11 106.98,23.19 106.6,23.19 106.53,23.27 106.53,23.52 106.6,23.6 106.98,23.6 107.06,23.67 107.06,23.93 106.98,24 106.6,24 106.53,24.08 106.53,24.33 106.6,24.41 106.98,24.41 107.06,24.49 107.06,24.74 106.98,24.82 106.6,24.82 106.53,24.89 106.53,25.15 106.6,25.22 107.06,25.22 107.14,25.3 107.14,26.31 110.64,29.81 110.64,42 109.22,43.42 109.22,44.09 U1.A4 ; 112.13,20.79 U12.H8 ; 112.13,20.79 112.14,20.79
DDR_BL0_DQ4: length 39.9
  TOP w0.102: U12.E3 116.14,18.39 116.56,18.81 118.69,18.81 118.8,18.71 119.02,18.71 119.15,18.83 119.88,18.83 119.98,18.94 119.98,19.27 120.35,19.64 121.09,19.64 121.23,19.79 121.23,27.42 115.67,32.98 115.67,43.33 113.15,45.85 111.93,45.85 111.09,46.69 110.26,46.69 110.12,46.83 109.93,46.83 109.59,46.49 U1.G4
DDR_BL0_DQ5: length 39.3
  TOP w0.102: U1.A6 108.55,44.09 108.55,43.23 110.03,41.74 110.03,30.07 108.64,28.68 105.99,28.68 105.92,28.6 105.92,28.24 105.99,28.17 106.98,28.17 107.06,28.09 107.06,27.76 106.98,27.69 105.99,27.69 105.92,27.61 105.92,27.33 105.99,27.25 106.63,27.25 106.71,27.18 106.71,26.92 106.63,26.85 105.99,26.85 105.92,26.77 105.92,26.42 105.99,26.34 106.45,26.34 106.53,26.26 106.53,25.93 106.45,25.86 105.99,25.86 105.92,25.78 105.92,19.68 105.99,19.6 110.43,19.6 110.51,19.52 111.11,19.52 111.19,19.6 111.73,19.6 112.14,19.19 U12.F8
DDR_BL0_DQ6: length 39.6
  TOP w0.102: U12.H3 116.14,20.79 116.53,21.18 117.98,21.18 118.16,21.36 120.05,21.36 120.2,21.51 120.2,26.91 120.12,26.99 119.05,26.99 118.97,27.06 118.97,27.28 119.05,27.36 119.62,27.36 119.69,27.43 119.69,27.67 119.6,27.76 118.34,27.76 118.26,27.84 118.26,28.09 118.34,28.17 118.77,28.17 118.88,28.28 118.88,28.48 118.73,28.63 118.16,28.63 118.07,28.73 118.07,29.29 114.76,32.6 114.76,38.96 114.68,39.04 113.61,39.04 113.51,39.14 113.51,40.18 113.59,40.26 114,40.26 114.07,40.34 114.07,40.59 114,40.67 113.59,40.67 113.51,40.74 113.51,41 113.59,41.07 114,41.07 114.07,41.15 114.07,41.48 114,41.55 113.59,41.55 113.51,41.63 113.51,44.19 112.62,45.09 111.83,45.09 110.93,45.98 U1.F1
DDR_BL0_DQ7: length 39.6
  TOP w0.102: U12.H7 112.94,20.79 112.54,21.18 111.94,21.18 111.72,21.4 111.72,21.86 111.62,21.96 107.52,21.96 107.39,22.09 107.39,23.76 107.46,23.83 107.49,23.83 107.49,23.84 108.23,23.84 108.33,23.94 108.33,24.18 108.25,24.26 107.47,24.26 107.39,24.33 107.39,24.64 107.47,24.71 108.89,24.71 108.97,24.79 108.97,25.04 108.89,25.12 107.52,25.12 107.44,25.2 107.44,25.43 107.54,25.53 108.82,25.53 108.9,25.6 108.9,25.86 108.82,25.93 107.71,25.93 107.6,26.04 107.6,26.34 110.95,29.69 110.95,42.22 110.48,42.69 110.48,44.03 110.06,44.45 110.06,44.97 109.96,45.07 109.58,45.07 109.51,45 108.96,45 U1.D5
DDR_BL0_LDM: length 38.4
  TOP w0.102: U1.C3 109.36,44.39 108.97,44.39 108.89,44.31 108.89,43.32 110.34,41.87 110.34,29.94 106.83,26.43 106.83,25.63 106.76,25.55 106.3,25.55 106.22,25.48 106.22,19.99 106.3,19.91 107.82,19.91 107.9,19.99 107.9,20.35 107.98,20.42 108.23,20.42 108.31,20.35 108.31,19.96 108.38,19.89 108.64,19.89 108.71,19.96 108.71,20.31 108.79,20.39 110.55,20.39 110.64,20.47 110.96,20.47 111.04,20.39 112.45,20.39 112.52,20.31 112.52,19.69 112.53,19.69 112.63,19.59 113.23,19.59 113.3,19.51 113.3,18.75 112.94,18.39 U12.E7
DDR_BL0_LDQS_N: length 39.2
  TOP w0.091: U12.G3 116.14,19.99 116.14,19.95 115.95,19.76 115.04,19.76 114.87,19.93 114.87,30.07 114.54,30.4 112.91,30.4 112.76,30.55 112.76,30.78 112.91,30.93 114,30.93 114.33,31.25 114.33,31.86 114.01,32.17 112.84,32.17 112.74,32.27 112.74,32.56 112.83,32.66 113.62,32.66 113.96,32.99 113.96,33.57 113.67,33.86 112.81,33.86 112.64,34.03 112.64,34.2 112.77,34.34 113.56,34.34 113.88,34.67 113.88,35.18 113.57,35.49 112.93,35.49 112.75,35.66 112.75,35.87 112.9,36.02 113.61,36.02 113.91,36.31 113.91,36.97 113.61,37.26 112.8,37.26 112.64,37.43 112.64,43.73 110.75,45.62 110.07,45.62 U1.D2
DDR_BL0_LDQS_P: length 39
  TOP w0.091: U12.F3 116.13,19.2 115.91,19.42 114.89,19.42 114.53,19.78 114.53,29.93 114.4,30.06 112.76,30.06 112.41,30.41 112.41,30.93 112.76,31.28 113.86,31.28 113.98,31.4 113.98,31.71 113.87,31.83 112.69,31.83 112.39,32.13 112.39,32.71 112.69,33 113.48,33 113.61,33.13 113.61,33.42 113.52,33.51 112.66,33.51 112.29,33.89 112.29,34.35 112.63,34.69 113.41,34.69 113.54,34.81 113.54,35.04 113.43,35.14 112.78,35.14 112.41,35.52 112.41,36.02 112.75,36.36 113.47,36.36 113.56,36.45 113.56,36.83 113.47,36.92 112.66,36.92 112.29,37.29 112.29,39.36 112.18,39.47 112.18,39.69 112.29,39.8 112.29,40.02 112.18,40.13 112.18,40.35 112.29,40.46 112.29,40.68 112.18,40.79 112.18,41.01 112.29,41.12 112.29,41.34 112.18,41.45 112.18,41.67 112.29,41.78 112.29,42 112.18,42.11 112.18,42.33 112.29,42.44 112.29,42.66 112.18,42.77 112.18,42.99 112.29,43.1 112.29,43.59 110.61,45.27 110.43,45.27 U1.D1
DDR_BL1_DQ8: length 65.2
  TOP w0.102: U12.C2 116.94,16.79 117.32,16.41 119,16.41 119.08,16.48 119.08,16.99 119.15,17.07 119.41,17.07 119.48,16.99 119.48,15.95 119.56,15.88 119.81,15.88 119.89,15.95 119.89,16.99 119.96,17.07 120.22,17.07 120.29,16.99 120.29,15.85 120.37,15.77 120.62,15.77 120.7,15.85 120.7,16.99 120.78,17.07 121.03,17.07 121.11,16.99 121.11,16.48 121.18,16.41 121.47,16.41 122.22,17.17 122.22,28.5 122.15,28.57 121.69,28.57 121.62,28.65 121.62,28.91 121.69,28.98 122.15,28.98 122.22,29.06 122.22,29.31 122.15,29.39 120.93,29.39 120.85,29.46 120.85,29.72 120.93,29.79 122.15,29.79 122.22,29.87 122.22,30.12 122.15,30.2 120.02,30.2 119.94,30.28 119.94,30.53 120.02,30.61 122.07,30.61 122.15,30.68 122.15,30.94 122.07,31.01 119.18,31.01 119.1,31.09 119.1,31.34 119.18,31.42 121.72,31.42 121.79,31.5 121.79,31.75 121.72,31.83 118.95,31.83 118.87,31.9 118.87,32.56 118.8,32.64 118.54,32.64 118.47,32.56 118.47,32.31 118.39,32.23 118.14,32.23 118.06,32.31 118.06,32.56 117.98,32.64 117.81,32.64 117.73,32.72 117.73,39.5 117.65,39.57 116.66,39.57 116.59,39.65 116.59,43.7 113.94,46.35 112.08,46.35 111.24,47.19 110.17,47.19 U1.J2
DDR_BL1_DQ9: length 65.6
  TOP w0.102: U1.N4 109.56,49.08 110.21,49.73 112.45,49.73 112.71,49.47 116.64,49.47 126.42,39.69 126.42,16.27 121.75,11.61 114.19,11.61 111.75,14.04 111.75,16.41 112.14,16.79 U12.C8
DDR_BL1_DQ10: length 65.6
  TOP w0.102: 116.13,15.2 116.14,15.19 ; 116.13,15.2 116.13,15.27 115.98,15.42 115.67,15.42 115.52,15.27 115.52,14.88 116.2,14.2 116.43,14.2 116.51,14.27 116.51,14.58 116.59,14.66 116.81,14.66 116.89,14.58 116.89,14.27 116.97,14.2 120.6,14.2 123.14,16.74 123.14,34.92 123.06,35 121.59,35 121.51,35.08 121.51,35.33 121.44,35.41 121.18,35.41 121.11,35.33 121.11,35.08 121.03,35 120.78,35 120.7,35.08 120.7,35.33 120.62,35.41 120.37,35.41 120.29,35.33 120.29,35.08 120.22,35 120.02,35 119.94,35.08 119.94,37.74 119.86,37.82 118.72,37.82 118.64,37.9 118.64,38.15 118.72,38.23 119.79,38.23 119.86,38.3 119.86,38.56 119.79,38.63 118.72,38.63 118.64,38.71 118.64,38.96 118.72,39.04 119.79,39.04 119.86,39.12 119.86,39.37 119.79,39.45 118.72,39.45 118.64,39.52 118.64,39.78 118.72,39.85 119.79,39.85 119.86,39.93 119.86,40.18 119.79,40.26 118.72,40.26 118.64,40.34 118.64,40.59 118.72,40.67 119.79,40.67 119.86,40.74 119.86,41 119.79,41.07 118.72,41.07 118.64,41.15 118.64,41.4 118.72,41.48 119.71,41.48 119.79,41.55 119.79,41.81 119.71,41.88 118.72,41.88 118.64,41.96 118.64,42.21 118.72,42.29 118.9,42.29 118.97,42.37 118.97,42.52 118.9,42.6 118.75,42.6 118.64,42.7 118.64,42.94 114.47,47.12 112.24,47.12 111.36,48.01 110.24,48.01 110.14,47.9 109.69,47.9 U1.K3 ; 116.13,15.2 U12.A3
DDR_BL1_DQ11: length 65
  TOP w0.102: U12.D7 112.94,17.59 113.15,17.8 113.63,17.8 113.72,17.88 113.72,18.29 113.82,18.39 114.15,18.39 114.25,18.29 114.25,17.88 114.33,17.8 114.73,17.8 114.78,17.86 114.78,18.44 114.86,18.52 115.19,18.52 115.27,18.44 115.27,14.77 116.14,13.89 120.75,13.89 123.44,16.59 123.44,36.22 123.37,36.3 123.11,36.3 123.04,36.22 123.04,35.38 122.96,35.31 122.71,35.31 122.63,35.38 122.63,36.25 122.56,36.32 122.3,36.32 122.22,36.25 122.22,35.38 122.15,35.31 121.89,35.31 121.82,35.38 121.82,35.99 121.74,36.07 121.31,36.07 120.95,35.71 120.35,35.71 120.24,35.81 120.24,36.32 120.32,36.4 120.83,36.4 120.9,36.47 120.9,36.83 120.83,36.91 120.35,36.91 120.24,37.01 120.24,37.34 120.32,37.41 120.8,37.41 120.88,37.49 120.88,37.85 120.8,37.92 120.32,37.92 120.24,38 120.24,41.77 114.64,47.37 112.28,47.37 111.44,48.21 110.01,48.21
  TOP w0.114: 110.01,48.21 U1.L2
DDR_BL1_DQ12: length 65.6
  TOP w0.102: U12.C3 116.14,16.79 116.56,16.36 116.56,15.79 116.78,15.57 117.12,15.57 117.35,15.34 117.35,15.06 117.6,14.81 120.31,14.81 122.53,17.02 122.53,32.97 122.45,33.05 122.2,33.05 122.12,32.97 122.12,32.26 122.05,32.18 121.79,32.18 121.72,32.26 121.72,32.99 121.64,33.07 121.39,33.07 121.31,32.99 121.31,32.26 121.23,32.18 120.98,32.18 120.9,32.26 120.9,32.99 120.83,33.07 120.57,33.07 120.5,32.99 120.5,32.26 120.42,32.18 120.17,32.18 120.09,32.26 120.09,32.97 120.02,33.05 119.76,33.05 119.68,32.97 119.68,32.26 119.61,32.18 119.35,32.18 119.28,32.26 119.28,32.84 119.18,32.94 118.16,32.94 118.06,33.05 118.06,33.35 118.14,33.43 118.39,33.43 118.47,33.5 118.47,33.83 118.39,33.91 118.16,33.91 118.06,34.01 118.06,34.29 118.14,34.37 118.39,34.37 118.47,34.44 118.47,34.7 118.39,34.77 118.11,34.77 118.03,34.85 118.03,39.8 117.96,39.88 116.97,39.88 116.89,39.95 116.89,40.18 116.97,40.26 117.96,40.26 118.03,40.34 118.03,40.59 117.96,40.67 116.93,40.67 116.89,40.71 116.89,41 116.97,41.07 117.96,41.07 118.03,41.15 118.03,41.4 117.96,41.48 116.94,41.48 116.89,41.53 116.89,41.81 116.97,41.88 117.96,41.88 118.03,41.96 118.03,42.21 117.96,42.29 116.97,42.29 116.89,42.37 116.89,42.62 116.97,42.7 117.58,42.7 117.65,42.77 117.65,43.03 117.58,43.1 116.97,43.1 116.89,43.18 116.89,43.83 114.11,46.61 112.18,46.61 111.34,47.45 110.36,47.45 110.11,47.7 109.94,47.7 109.59,47.36 U1.J4
DDR_BL1_DQ13: length 65.3
  TOP w0.102: U12.B8 112.14,15.99 112.14,15.79 112.55,15.38 112.55,14.78 112.65,14.68 113.13,14.68 113.21,14.61 113.21,14.38 113.11,14.27 112.6,14.27 112.39,14.07 112.39,13.79 112.5,13.69 113.09,13.69 113.26,13.53 113.26,13.4 113.11,13.25 113.11,13.12 113.29,12.93 113.45,12.93 113.88,13.36 114.03,13.36 114.22,13.17 114.22,13.02 113.77,12.56 113.77,12.46 114.02,12.21 114.14,12.21 114.53,12.6 114.76,12.6 114.91,12.45 114.91,12.06 115.06,11.91 121.62,11.91 126.11,16.4 126.11,39.57 116.44,49.24 112.53,49.24 112.26,49.51 U1.P1
DDR_BL1_DQ14: length 64.7
  TOP w0.102: U12.A2 116.94,15.19 116.94,15.07 117.5,14.5 120.46,14.5 122.83,16.88 122.83,34.49 122.76,34.57 122.5,34.57 122.43,34.49 122.43,33.55 122.35,33.48 122.1,33.48 122.02,33.55 122.02,34.52 121.95,34.59 121.69,34.59 121.62,34.52 121.62,33.55 121.54,33.48 121.28,33.48 121.21,33.55 121.21,34.52 121.13,34.59 120.88,34.59 120.8,34.52 120.8,33.55 120.73,33.48 120.47,33.48 120.4,33.55 120.4,34.49 120.32,34.57 120.07,34.57 119.99,34.49 119.99,33.55 119.91,33.48 119.66,33.48 119.58,33.55 119.58,34.87 119.51,34.95 119.25,34.95 119.18,34.87 119.18,33.55 119.1,33.48 118.85,33.48 118.77,33.55 118.77,35 118.69,35.08 118.47,35.08 118.39,35.15 118.39,35.41 118.47,35.48 119.43,35.48 119.51,35.56 119.51,35.81 119.43,35.89 118.47,35.89 118.39,35.97 118.39,36.22 118.47,36.3 119.43,36.3 119.51,36.37 119.51,36.63 119.43,36.7 118.47,36.7 118.39,36.78 118.39,37.06 118.47,37.13 119.48,37.13 119.56,37.21 119.56,37.44 119.48,37.52 118.41,37.52 118.34,37.59 118.34,42.81 114.29,46.86 112.21,46.86 111.29,47.79 U1.K1
DDR_BL1_DQ15: length 65.5
  TOP w0.102: 112.94,15.19 112.94,15.19 ; 112.94,15.19 U12.A7 ; 112.94,15.19 112.94,15.39 112.53,15.8 112.53,17.04 112.69,17.19 114.84,17.19 115.01,17.02 115.01,14.66 116.08,13.59 120.89,13.59 123.75,16.45 123.75,38.13 123.67,38.2 123.14,38.2 123.06,38.13 123.06,36.86 122.99,36.78 122.61,36.78 122.53,36.86 122.53,38.13 122.45,38.2 122.07,38.2 122,38.13 122,36.86 121.92,36.78 121.54,36.78 121.46,36.86 121.46,38.2 121.39,38.28 120.62,38.28 120.55,38.35 120.55,41.9 114.82,47.62 112.31,47.62 111.52,48.41 110.26,48.41 110.13,48.54 109.91,48.54 109.59,48.22 U1.L4
DDR_BL1_UDM: length 64.9
  TOP w0.102: U1.H1 111.19,46.92 112.01,46.1 113.68,46.1 116.28,43.5 116.28,39.32 116.36,39.24 117.35,39.24 117.42,39.17 117.42,38.91 117.35,38.84 116.36,38.84 116.28,38.76 116.28,38.51 116.36,38.43 117.35,38.43 117.42,38.35 117.42,38.1 117.35,38.02 116.36,38.02 116.28,37.95 116.28,37.69 116.36,37.62 117.35,37.62 117.42,37.54 117.42,37.29 117.35,37.21 116.36,37.21 116.28,37.13 116.28,36.88 116.36,36.8 117.35,36.8 117.42,36.73 117.42,36.47 117.35,36.4 116.48,36.4 116.41,36.32 116.41,36.07 116.48,35.99 117.35,35.99 117.42,35.92 117.42,35.66 117.35,35.59 116.46,35.59 116.38,35.51 116.38,35.26 116.46,35.18 117.35,35.18 117.42,35.1 117.42,34.85 117.35,34.77 116.48,34.77 116.41,34.7 116.41,34.44 116.48,34.37 117.35,34.37 117.42,34.29 117.42,34.04 117.35,33.96 116.51,33.96 116.41,33.86 116.41,33.63 116.48,33.55 117.35,33.55 117.42,33.48 117.42,33.22 117.35,33.15 116.71,33.15 116.64,33.07 116.64,32.82 116.71,32.74 117.35,32.74 117.42,32.66 117.42,32.3 121.93,27.8 121.93,19.1 121.86,19.02 121.11,19.02 121.03,18.95 121.03,18.69 121.11,18.62 121.86,18.62 121.93,18.54 121.93,18.29 121.86,18.21 121.34,18.21 121.26,18.14 121.26,17.88 121.34,17.81 121.86,17.81 121.93,17.73 121.93,17.45 121.86,17.37 120.88,17.37 120.8,17.45 120.8,18.16 120.73,18.24 120.47,18.24 120.4,18.16 120.4,17.45 120.32,17.37 120.07,17.37 119.99,17.45 119.99,18.16 119.91,18.24 119.66,18.24 119.58,18.16 119.58,17.45 119.51,17.37 119.25,17.37 119.18,17.45 119.18,18.16 119.1,18.24 118.85,18.24 118.77,18.16 118.77,17.45 118.69,17.37 118.22,17.37 118.06,17.22 116.51,17.22 116.14,17.59 U12.D3
DDR_BL1_UDQS_N: length 64.8
  TOP w0.091: U1.N2 110.18,49.25 111.97,49.25 112.39,48.82 115.54,48.82 121.87,42.49 121.87,39.91 121.96,39.81 124.89,39.81 125.34,39.36 125.34,38.33 125.34,38.14 124.93,37.74 124.93,37.47 125.35,37.06 125.35,36.29 125.01,35.94 125.01,35.68 125.47,35.21 125.47,34.68 125.12,34.33 125.12,33.8 125.48,33.44 125.48,32.83 125.01,32.36 125.01,31.91 125.41,31.5 125.41,30.98 125.06,30.63 125.06,30.09 125.48,29.67 125.48,29.15 124.87,28.55 124.87,28.18 125.41,27.64 125.41,27.11 124.93,26.63 124.93,26.25 125.35,25.84 125.35,24.97 124.93,24.56 124.93,24.17 125.55,23.55 125.55,22.98 124.93,22.36 124.93,22.1 125.41,21.62 125.41,20.89 124.87,20.34 124.87,19.9 125.38,19.4 125.38,18.59 124.81,18.02 124.81,17.61 125.25,17.16 125.25,16.43 121.43,12.61 115.62,12.61 114.05,14.18 114.05,16 113.79,16.26 113.2,16.26 U12.B7
DDR_BL1_UDQS_P: length 64.8
  TOP w0.091: U1.M3 109.7,48.77 110.16,48.77 110.29,48.91 111.82,48.91 112.25,48.48 115.4,48.48 116.83,47.05 116.83,46.88 116.98,46.72 117.15,46.72 117.31,46.57 117.31,46.39 117.46,46.24 117.64,46.24 117.79,46.09 117.79,45.91 117.95,45.76 118.12,45.76 118.27,45.6 118.27,45.43 118.43,45.28 118.6,45.28 118.75,45.12 118.75,44.95 118.91,44.79 119.08,44.79 119.24,44.64 119.24,44.47 119.39,44.31 119.56,44.31 119.72,44.16 119.72,43.98 119.87,43.83 120.05,43.83 121.52,42.35 121.52,39.76 121.82,39.47 124.74,39.47 124.99,39.22 124.99,38.33 124.99,38.29 124.59,37.88 124.59,37.33 125,36.92 125,36.43 124.86,36.29 124.86,36.29 124.66,36.09 124.66,35.54 125.13,35.07 125.13,34.82 124.78,34.47 124.78,33.65 125.13,33.3 125.13,32.97 124.86,32.71 124.86,32.71 124.66,32.5 124.66,31.77 125.06,31.36 125.06,31.12 124.71,30.77 124.71,29.94 125.13,29.53 125.13,29.3 124.73,28.9 124.73,28.9 124.53,28.69 124.53,28.03 125.06,27.49 125.06,27.25 124.59,26.77 124.59,26.11 125,25.69 125,25.12 124.59,24.7 124.59,24.03 125.21,23.41 125.21,23.13 124.59,22.51 124.59,21.96 125.07,21.48 125.07,21.03 124.52,20.49 124.52,19.76 125.03,19.25 125.03,18.73 124.46,18.16 124.46,17.46 124.9,17.02 124.9,16.57 121.29,12.95 115.76,12.95 114.39,14.32 114.39,16.15 113.94,16.6 113.12,16.6 U12.C7
DDR_BL2_DQ16: length 41.2
  TOP w0.102: U1.A25 100.39,44.09 100.41,44.11 100.41,43.1 99.14,41.82 99.14,31.39 99.21,31.32 102.06,31.32 102.18,31.19 102.18,25.02 102.11,24.94 101.5,24.94 101.42,24.87 101.42,24.56 101.5,24.49 102.08,24.49 102.16,24.41 102.16,24.16 102.08,24.08 101.5,24.08 101.42,24 101.42,23.72 101.5,23.65 102.01,23.65 102.08,23.57 102.08,23.34 102.01,23.27 101.5,23.27 101.42,23.19 101.42,22.89 101.5,22.81 101.98,22.81 102.06,22.73 102.06,22.43 101.98,22.35 101.5,22.35 101.42,22.28 101.42,21.97 101.5,21.89 101.96,21.89 102.03,21.82 102.03,21.51 101.96,21.44 101.5,21.44 101.42,21.36 101.42,21.06 101.5,20.98 101.96,20.98 102.03,20.9 102.03,20.6 101.96,20.52 101.5,20.52 101.42,20.45 101.42,18.92 100.48,17.98 96.17,17.98 95.77,18.39 U13.E3
DDR_BL2_DQ17: length 41.3
  TOP w0.102: U1.C28 99.19,44.76 99.18,44.75 99.4,44.53 99.4,43.25 98.22,42.08 98.22,28.52 98.37,28.37 98.68,28.37 98.76,28.45 98.76,28.68 98.83,28.75 99.09,28.75 99.16,28.68 99.16,28.45 99.24,28.37 99.49,28.37 99.57,28.45 99.57,28.68 99.64,28.75 99.9,28.75 99.97,28.68 99.97,28.45 100.05,28.37 100.43,28.37 100.51,28.3 100.51,20.42 100.36,20.27 97.94,20.27 97.82,20.38 96.43,20.38 96.17,20.13 96.17,18.88 96.09,18.79 95.38,18.79 95.29,18.7 95.29,18.39 95.22,18.31 94.97,18.31 94.89,18.39 94.89,18.71 94.81,18.79 94.58,18.79 94.49,18.71 94.49,18.4 94.41,18.31 94.16,18.31 94.08,18.4 94.08,19.06 93.99,19.15 93.76,19.15 93.68,19.07 93.68,18.31 93.58,18.21 93.35,18.21 93.27,18.3 93.27,19.02 93.18,19.1 92.65,19.1 92.57,19.19 U13.F7
DDR_BL2_DQ18: length 41
  TOP w0.102: U13.F2 96.57,19.19 96.96,18.79 97.71,18.79 97.74,18.82 98.58,18.82 98.6,18.79 100.76,18.79 101.12,19.15 101.12,26.24 101.19,26.31 101.73,26.31 101.8,26.39 101.8,26.7 101.73,26.77 101.19,26.77 101.12,26.85 101.12,27.18 101.19,27.25 101.73,27.25 101.8,27.33 101.8,27.58 101.73,27.66 101.19,27.66 101.12,27.74 101.12,27.99 101.19,28.07 101.75,28.07 101.83,28.14 101.83,28.4 101.75,28.47 101.19,28.47 101.12,28.55 101.12,28.8 101.19,28.88 101.8,28.88 101.88,28.96 101.88,29.21 101.8,29.29 101.19,29.29 101.12,29.36 101.12,29.62 101.19,29.69 101.8,29.69 101.88,29.77 101.88,30.02 101.8,30.1 101.19,30.1 101.12,30.18 101.12,30.43 101.19,30.51 101.8,30.51 101.88,30.58 101.88,30.91 101.8,30.99 98.91,30.99 98.83,31.06 98.83,41.88 100.06,43.11 100.06,44.41 99.79,44.68 U1.B26
DDR_BL2_DQ19: length 41.9
  TOP w0.102: U13.H8 91.76,20.79 91.34,21.22 90.47,21.22 88.6,23.09 88.6,24.13 88.31,24.41 87.33,24.41 86.94,24.79 86.94,26.77 87.1,26.92 88.54,26.92 88.62,27 88.62,28.37 88.7,28.45 89.53,28.45 89.61,28.52 89.61,28.8 89.53,28.88 88.7,28.88 88.62,28.96 88.62,29.21 88.7,29.29 89.43,29.29 89.51,29.36 89.51,29.62 89.43,29.69 88.82,29.69 88.75,29.77 88.75,30.19 88.84,30.28 93.57,30.28 93.65,30.35 93.65,42.67 96.57,45.59 97.64,45.59 98.33,46.28 98.67,46.28 99,45.94 U1.F27
DDR_BL2_DQ20: length 41.5
  TOP w0.102: U1.D25 99.95,45.07 98.98,45.07 98.88,44.97 98.88,44.45 98.63,44.2 98.63,43.81 97.92,43.1 97.92,28.22 98.07,28.07 100.05,28.07 100.13,27.99 100.13,27.74 100.05,27.66 99.21,27.66 99.13,27.58 99.13,27.33 99.21,27.25 100.05,27.25 100.13,27.18 100.13,24.56 99.97,24.41 99.06,24.41 98.98,24.33 98.98,24.08 99.06,24 100.05,24 100.13,23.93 100.13,23.67 100.05,23.6 99.14,23.6 99.06,23.52 99.06,23.27 99.14,23.19 100.05,23.19 100.13,23.11 100.13,22.86 100.05,22.78 99.14,22.78 99.06,22.71 99.06,22.45 99.14,22.38 99.97,22.38 100.05,22.3 100.05,22.05 99.97,21.97 99.21,21.97 99.14,21.89 99.14,21.64 99.21,21.56 99.92,21.56 100,21.49 100,21.26 99.94,21.2 96.17,21.2 95.77,20.79 U13.H3
DDR_BL2_DQ21: length 41.8
  TOP w0.102: U1.G26 99.35,46.49 99.04,46.8 98.79,46.8 98.68,46.69 98.16,46.69 97.47,46 96.11,46 93.04,42.93 93.04,32.26 91.67,30.89 88.32,30.89 88,30.57 88,28.05 87.48,27.53 86.69,27.53 86.33,27.18 86.33,24.71 87.19,23.86 87.9,23.86 88.11,23.65 88.11,22.91 89.61,21.41 89.61,19.12 90.03,18.7 90.44,18.7 90.52,18.78 91.36,18.78 91.77,19.19 U13.F8
DDR_BL2_DQ22: length 40.7
  TOP w0.102: U13.G2 96.57,19.99 96.57,19.71 96.69,19.59 97.76,19.59 97.88,19.71 98.32,19.71 98.83,19.2 100.48,19.2 100.81,19.53 100.81,30.58 100.74,30.66 99.85,30.66 99.77,30.58 99.77,30.38 99.85,30.3 100.3,30.3 100.38,30.23 100.38,29.97 100.3,29.9 99.85,29.9 99.77,29.82 99.77,29.57 99.85,29.49 100.3,29.49 100.38,29.41 100.38,29.13 100.3,29.06 99.44,29.06 99.36,29.13 99.36,30.66 99.29,30.73 99.03,30.73 98.96,30.66 98.96,29.13 98.88,29.06 98.6,29.06 98.53,29.13 98.53,42.01 99.71,43.2 99.71,44.09 U1.A26
DDR_BL2_DQ23: length 40.9
  TOP w0.102: U1.F29 98.32,45.98 97.72,45.39 96.8,45.39 93.95,42.55 93.95,30.05 93.88,29.97 91.06,29.97 90.98,29.9 90.98,28.09 90.91,28.02 89.08,28.02 89,27.94 89,27.23 89.08,27.15 89.84,27.15 89.92,27.08 89.92,26.16 89.84,26.09 89.15,26.09 89.08,26.16 89.08,26.54 89,26.62 87.4,26.62 87.25,26.47 87.25,24.81 87.41,24.65 88.51,24.65 88.82,24.33 88.82,23.19 90.04,21.97 92.07,21.97 92.16,21.88 92.16,21.4 92.57,21 92.57,20.79 U13.H7
DDR_BL2_LDM: length 41.2
  TOP w0.102: U13.E7 92.57,18.39 92.18,18.78 92.18,19.41 92,19.58 90.49,19.58 90.41,19.66 90.04,19.66 89.92,19.79 89.92,21.44 88.37,22.99 88.37,23.96 88.2,24.13 87.24,24.13 86.64,24.74 86.64,27.03 86.84,27.23 88.16,27.23 88.32,27.38 88.32,30.38 88.52,30.58 91.92,30.58 93.34,32 93.34,42.8 96.34,45.8 97.56,45.8 98.24,46.48 98.91,46.48 U1.G28
DDR_BL2_LDQS_N: length 40.3
  TOP w0.091: U13.G3 95.78,19.97 95.78,19.82 95.69,19.73 95.05,19.73 94.58,20.2 94.58,20.79 94.68,20.89 94.68,21.11 94.58,21.21 94.58,21.43 94.68,21.53 94.68,21.74 94.58,21.84 94.58,22.18 94.33,22.43 94.33,22.78 94.42,22.88 94.42,23.1 94.33,23.2 94.33,23.41 94.42,23.51 94.42,23.73 94.33,23.83 94.33,24.05 94.42,24.15 94.42,24.37 94.33,24.47 94.33,24.68 94.42,24.78 94.42,25 94.33,25.1 94.33,25.32 94.42,25.42 94.42,25.64 94.33,25.74 94.33,25.95 94.42,26.05 94.42,26.27 94.33,26.37 94.33,26.59 94.42,26.69 94.42,26.91 94.33,27.01 94.33,27.22 94.42,27.32 94.42,27.54 94.33,27.64 94.33,27.86 94.42,27.96 94.42,28.18 94.33,28.28 94.33,28.56 94.57,28.81 94.72,28.81 94.87,28.96 94.87,29.11 95.03,29.26 95.18,29.26 95.33,29.42 95.33,29.56 95.63,29.86 95.63,30.25 95.76,30.38 95.76,30.6 95.63,30.73 95.63,30.95 95.76,31.07 95.76,31.29 95.63,31.42 95.63,31.64 95.76,31.76 95.76,31.98 95.63,32.11 95.63,32.46 95.72,32.55 96.41,32.55 96.71,32.85 96.71,33.73 96.41,34.04 95.69,34.04 95.6,34.14 95.6,34.57 95.69,34.67 96.44,34.67 96.74,34.96 96.74,35.58 96.41,35.91 95.69,35.91 95.6,36 95.6,36.36 95.69,36.45 96.44,36.45 96.74,36.74 96.74,37.58 96.44,37.87 95.62,37.87 95.53,37.97 95.53,38.39 95.62,38.48 96.44,38.48 96.74,38.77 96.74,39.7 96.41,40.03 95.56,40.03 95.47,40.12 95.47,40.6 95.57,40.7 96.48,40.7 96.77,41 96.77,41.77 96.48,42.06 95.72,42.06 95.63,42.16 95.63,42.61 95.76,42.74 96.7,42.74 96.99,43.03 96.99,43.27 97.09,43.37 97.09,43.59 96.99,43.69 96.99,43.91 97.29,44.21 97.49,44.21 97.64,44.36 97.64,44.55 97.79,44.71 97.98,44.71 98.14,44.86 98.14,45.05 98.38,45.29 U1.D29
DDR_BL2_LDQS_P: length 40.4
  TOP w0.091: U1.D28 98.84,45.63 98.52,45.63 98.51,45.64 98.23,45.64 96.65,44.05 96.65,43.17 96.56,43.08 95.61,43.08 95.29,42.75 95.29,42.01 95.58,41.72 96.34,41.72 96.43,41.63 96.43,41.14 96.34,41.05 95.42,41.05 95.12,40.75 95.12,39.98 95.42,39.69 96.27,39.69 96.39,39.56 96.39,38.92 96.3,38.83 95.48,38.83 95.19,38.53 95.19,37.82 95.48,37.53 96.3,37.53 96.39,37.44 96.39,36.89 96.3,36.79 95.54,36.79 95.25,36.5 95.25,35.85 95.54,35.56 96.27,35.56 96.39,35.43 96.39,35.11 96.3,35.02 95.55,35.02 95.25,34.72 95.25,33.99 95.55,33.69 96.26,33.69 96.37,33.59 96.37,33 96.26,32.89 95.58,32.89 95.29,32.6 95.29,30.01 93.98,28.7 93.98,22.29 94.23,22.04 94.23,20.06 94.91,19.38 95.67,19.38 95.76,19.29 U13.F3
DDR_BL3_DQ24: length 67.6
  TOP w0.102: U13.C2 96.57,16.79 96.16,16.39 96.16,15.73 96.29,15.6 96.89,15.6 96.98,15.51 96.98,14.85 96.89,14.76 96.2,14.76 96.11,14.67 96.11,14.44 96.2,14.35 97.56,14.35 97.64,14.27 97.64,14.02 97.56,13.94 96.19,13.94 96.11,13.87 96.11,13.62 96.2,13.54 96.66,13.54 96.73,13.46 96.73,13.13 96.63,13.02 96.22,13.02 96.12,12.93 96.12,12.52 95.36,11.76 89.69,11.76 82.07,19.39 82.07,37.64 93.9,49.47 96.06,49.47 96.58,48.95 96.99,48.95 97.13,49.08 U1.N28
DDR_BL3_DQ25: length 67.4
  TOP w0.102: U13.A7 92.57,15.19 92.19,14.81 90.63,14.81 88.54,16.89 88.54,20.66 85.12,24.09 85.12,32.11 85.19,32.18 89.08,32.18 89.15,32.26 89.15,34.49 89.23,34.57 89.93,34.57 90,34.65 90,34.9 89.93,34.98 89.23,34.98 89.15,35.05 89.15,35.31 89.23,35.38 90.6,35.38 90.68,35.46 90.68,35.71 90.6,35.79 89.23,35.79 89.15,35.86 89.15,36.12 89.23,36.2 90.6,36.2 90.68,36.27 90.68,36.53 90.6,36.6 89.23,36.6 89.15,36.68 89.15,36.93 89.23,37.01 90.6,37.01 90.68,37.08 90.68,37.34 90.6,37.41 89.23,37.41 89.15,37.49 89.15,37.74 89.23,37.82 90.6,37.82 90.68,37.9 90.68,38.15 90.6,38.23 89.23,38.23 89.15,38.3 89.15,38.56 89.23,38.63 90.6,38.63 90.68,38.71 90.68,38.96 90.6,39.04 89.23,39.04 89.15,39.12 89.15,39.37 89.23,39.45 90.6,39.45 90.68,39.52 90.68,39.78 90.6,39.85 89.23,39.85 89.15,39.93 89.15,40.18 89.23,40.26 90.6,40.26 90.66,40.32 90.66,40.64 90.58,40.72 90.07,40.72 89.99,40.79 89.99,41.1 90.07,41.17 90.58,41.17 90.66,41.25 90.66,42.16 95.11,46.61 97.22,46.61 97.97,47.36 U1.J28
